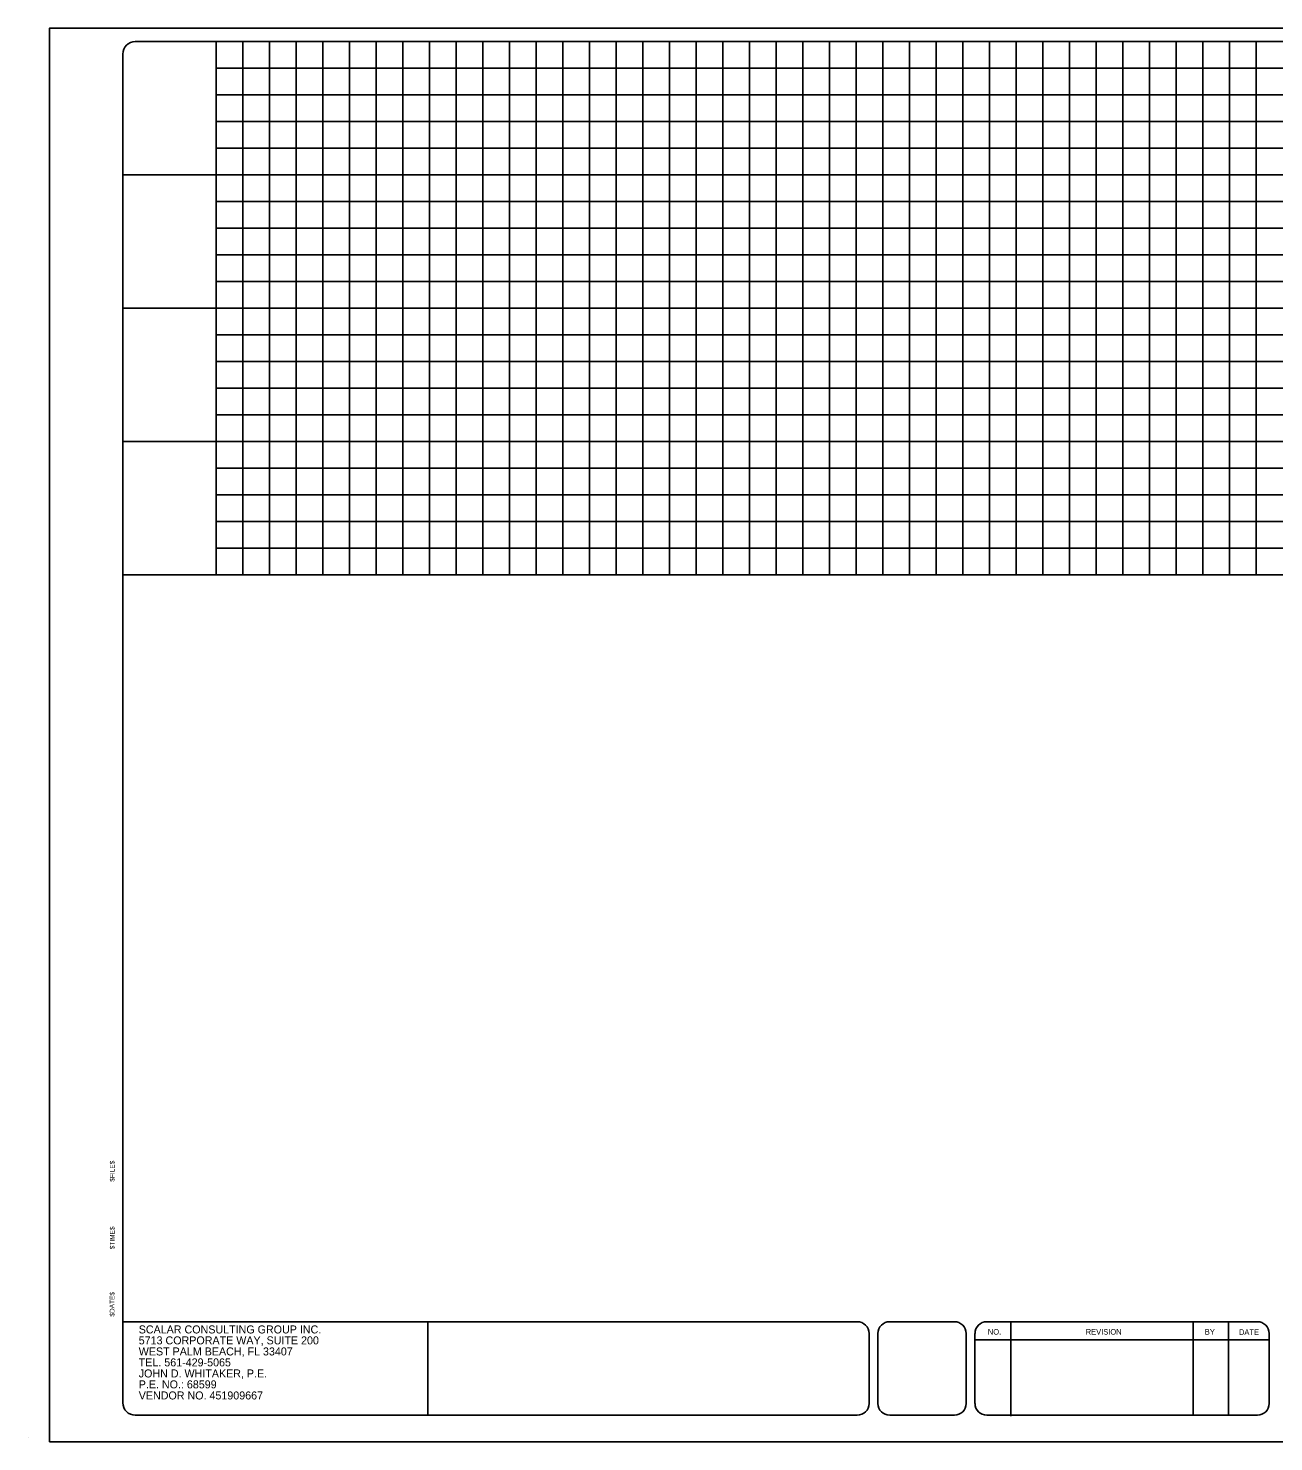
# Model space of a CAD drawing. Extents: x -1.5 to 15.2, y -6.5 to 4.1.
# Drawn here: x -1.46 to 7.88, y -6.49 to 4.11 of the extents above; entities that cross this region are included whole.
import ezdxf

# ---------------------------------------------------------------- set-up
doc = ezdxf.new("R2010")
doc.units = 0
for name, color, linetype in [('AdhocPoint_dp', 7, 'Continuous'), ('Default', 7, 'Continuous'), ('GridMaj_dp', 7, 'Continuous'), ('GridMin_dp', 7, 'Continuous'), ('PlotBorder_dp', 7, 'Continuous')]:
    doc.layers.add(name, color=color, linetype=linetype)

msp = doc.modelspace()

# ---------------------------------------------------------------- linework, layer by layer
at = {"layer": 'AdhocPoint_dp'}
msp.add_line((-1.457, -6.46), (-1.457, -6.46), dxfattribs=at)
at = {"layer": 'Default'}
for p, q in [((14.576, 4.01), (-0.655, 4.01)), ((-0.749, -6.198), (-0.749, 3.916)), ((4.759, -5.59), (-0.749, -5.59)), ((1.54, -6.291), (1.54, -5.59)), ((5.487, -5.59), (5.002, -5.59)), ((7.759, -5.59), (5.73, -5.59)), ((5.91, -5.594), (5.91, -6.299)), ((7.277, -5.594), (7.277, -6.291)), ((7.542, -5.594), (7.542, -6.291)), ((4.847, -5.678), (4.847, -6.203)), ((4.914, -5.678), (4.914, -6.203)), ((5.575, -5.678), (5.575, -6.203)), ((5.641, -5.678), (5.641, -6.203)), ((7.847, -5.678), (7.847, -6.203)), ((7.85, -5.726), (5.645, -5.726)), ((4.759, -6.291), (-0.655, -6.291)), ((5.487, -6.291), (5.002, -6.291)), ((7.759, -6.291), (5.73, -6.291))]:
    msp.add_line(p, q, dxfattribs=at)
for centre, major_axis, start_param, end_param in [((-0.655, 3.916), (0, -0.0935), 3.141593, 4.712389), ((4.759, -5.678), (0, 0.0882), 4.712389, 6.283185), ((5.002, -5.678), (0, 0.0882), 0, 1.570796), ((5.487, -5.678), (0, 0.0882), 4.712389, 6.283185), ((5.73, -5.678), (0, 0.0882), 0, 1.570796), ((7.759, -5.678), (0, 0.0882), 4.712389, 6.283185), ((-0.655, -6.198), (0, -0.0935), 4.712389, 6.283185), ((4.759, -6.203), (0, 0.0882), 3.141593, 4.712389), ((5.002, -6.203), (0, -0.0882), 4.712389, 6.283185), ((5.487, -6.203), (0, 0.0882), 3.141593, 4.712389), ((5.73, -6.203), (0, -0.0882), 4.712389, 6.283185), ((7.759, -6.203), (0, 0.0882), 3.141593, 4.712389)]:
    msp.add_ellipse(centre, major_axis=major_axis, ratio=0.999927, start_param=start_param, end_param=end_param, dxfattribs=at)
at = {"layer": 'GridMaj_dp'}
for p, q in [((-0.049, 0.01), (-0.049, 4.01)), ((0.951, 0.01), (0.951, 4.01)), ((1.951, 0.01), (1.951, 4.01)), ((2.951, 0.01), (2.951, 4.01)), ((3.951, 0.01), (3.951, 4.01)), ((4.951, 0.01), (4.951, 4.01)), ((5.951, 0.01), (5.951, 4.01)), ((6.951, 0.01), (6.951, 4.01)), ((-0.749, 3.01), (14.651, 3.01)), ((-0.749, 2.01), (14.651, 2.01)), ((-0.749, 1.01), (14.651, 1.01)), ((-0.749, 0.01), (14.651, 0.01))]:
    msp.add_line(p, q, dxfattribs=at)
at = {"layer": 'GridMin_dp'}
for p, q in [((0.151, 0.01), (0.151, 4.01)), ((0.351, 0.01), (0.351, 4.01)), ((0.551, 0.01), (0.551, 4.01)), ((0.751, 0.01), (0.751, 4.01)), ((1.151, 0.01), (1.151, 4.01)), ((1.351, 0.01), (1.351, 4.01)), ((1.551, 0.01), (1.551, 4.01)), ((1.751, 0.01), (1.751, 4.01)), ((2.151, 0.01), (2.151, 4.01)), ((2.351, 0.01), (2.351, 4.01)), ((2.551, 0.01), (2.551, 4.01)), ((2.751, 0.01), (2.751, 4.01)), ((3.151, 0.01), (3.151, 4.01)), ((3.351, 0.01), (3.351, 4.01)), ((3.551, 0.01), (3.551, 4.01)), ((3.751, 0.01), (3.751, 4.01)), ((4.151, 0.01), (4.151, 4.01)), ((4.351, 0.01), (4.351, 4.01)), ((4.551, 0.01), (4.551, 4.01)), ((4.751, 0.01), (4.751, 4.01)), ((5.151, 0.01), (5.151, 4.01)), ((5.351, 0.01), (5.351, 4.01)), ((5.551, 0.01), (5.551, 4.01)), ((5.751, 0.01), (5.751, 4.01)), ((6.151, 0.01), (6.151, 4.01)), ((6.351, 0.01), (6.351, 4.01)), ((6.551, 0.01), (6.551, 4.01)), ((6.751, 0.01), (6.751, 4.01)), ((7.151, 0.01), (7.151, 4.01)), ((7.351, 0.01), (7.351, 4.01)), ((7.551, 0.01), (7.551, 4.01)), ((7.751, 0.01), (7.751, 4.01)), ((-0.049, 3.81), (13.951, 3.81)), ((-0.049, 3.61), (13.951, 3.61)), ((-0.049, 3.41), (13.951, 3.41)), ((-0.049, 3.21), (13.951, 3.21)), ((-0.049, 2.81), (13.951, 2.81)), ((-0.049, 2.61), (13.951, 2.61)), ((-0.049, 2.41), (13.951, 2.41)), ((-0.049, 2.21), (13.951, 2.21)), ((-0.049, 1.81), (13.951, 1.81)), ((-0.049, 1.61), (13.951, 1.61)), ((-0.049, 1.41), (13.951, 1.41)), ((-0.049, 1.21), (13.951, 1.21)), ((-0.049, 0.81), (13.951, 0.81)), ((-0.049, 0.61), (13.951, 0.61)), ((-0.049, 0.41), (13.951, 0.41)), ((-0.049, 0.21), (13.951, 0.21))]:
    msp.add_line(p, q, dxfattribs=at)
at = {"layer": 'PlotBorder_dp'}
msp.add_lwpolyline([(-1.299, -6.49), (15.201, -6.49), (15.201, 4.11), (-1.299, 4.11)], close=True, dxfattribs=at)
msp.add_lwpolyline([(-1.299, -6.49), (15.201, -6.49), (15.201, 4.11), (-1.299, 4.11)], close=True, dxfattribs=at)

# ---------------------------------------------------------------- texts
at = {"layer": 'Default'}
for s, p in [('$FILE$', (-0.81, -4.54)), ('$TIME$', (-0.81, -5.047)), ('$DATE$', (-0.811, -5.552))]:
    msp.add_text(s, height=0.0354, rotation=90, dxfattribs=at).set_placement(p)
for s, height, p in [('SCALAR CONSULTING GROUP INC.', 0.06, (-0.629, -5.678)), ('5713 CORPORATE WAY, SUITE 200', 0.06, (-0.629, -5.76)), ('NO.', 0.0421, (5.738, -5.687)), ('REVISION', 0.0421, (6.472, -5.687)), ('BY', 0.0421, (7.365, -5.687)), ('DATE', 0.0421, (7.621, -5.689)), ('WEST PALM BEACH, FL 33407', 0.06, (-0.629, -5.843)), ('TEL. 561-429-5065', 0.06, (-0.629, -5.925)), ('JOHN D. WHITAKER, P.E.', 0.06, (-0.629, -6.008)), ('P.E. NO.: 68599', 0.06, (-0.629, -6.09)), ('VENDOR NO. 451909667', 0.06, (-0.629, -6.173))]:
    msp.add_text(s, height=height, dxfattribs=at).set_placement(p)

doc.saveas('drawing.dxf')
